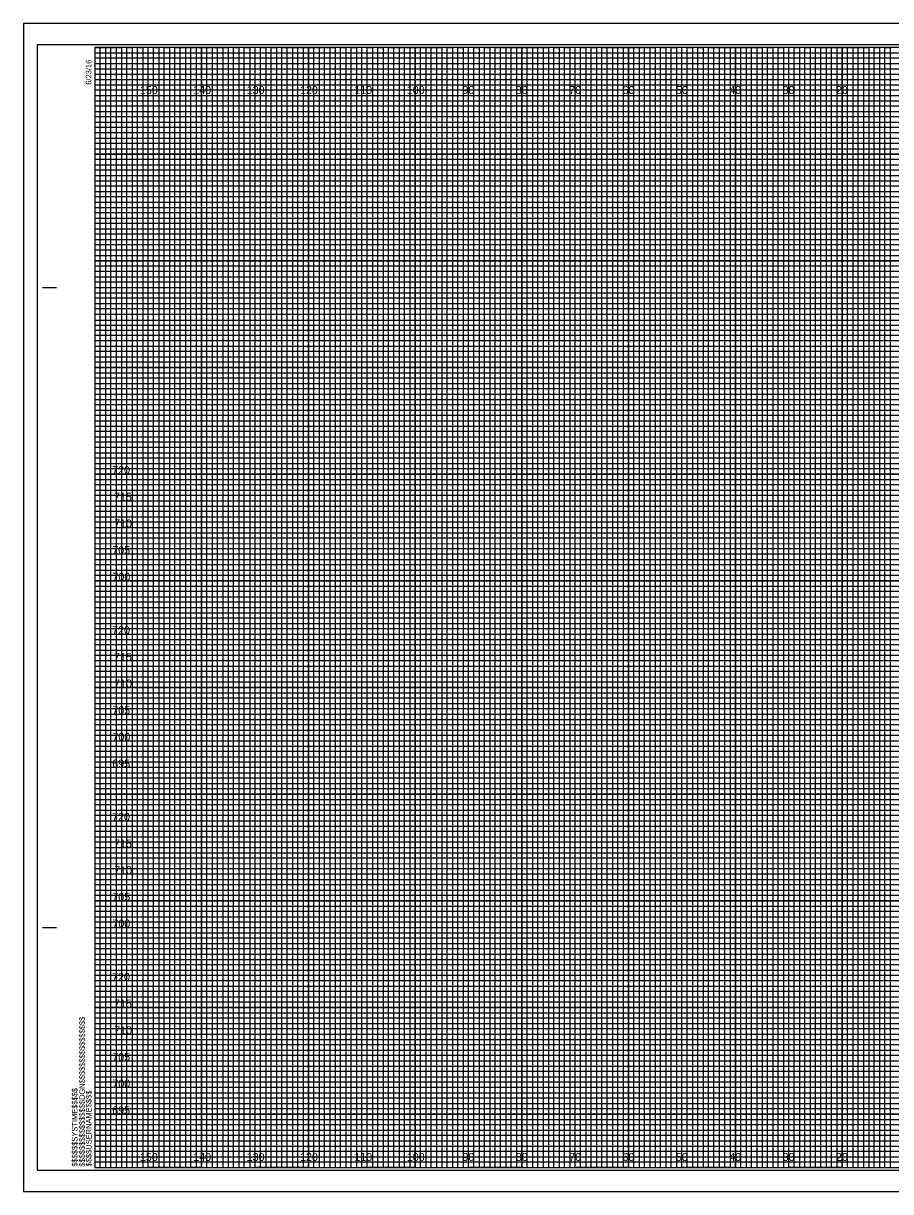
# Model space of a CAD drawing. Extents: x -13 to 323, y -5 to 434.
# Drawn here: x -13.4 to 149.1, y 215.5 to 434.5 of the extents above; entities that cross this region are included whole.
import ezdxf

# ---------------------------------------------------------------- set-up
doc = ezdxf.new("R2010")
doc.units = 0
for name, color, linetype in [('Exist CMT Pavement', 7, 'Continuous'), ('Exist Cross Section Cell', 7, 'Continuous'), ('Exist XS Center Line Elevation Label', 7, 'Continuous'), ('Exist XS Ground Line', 7, 'Continuous'), ('Prop CMT Pvmt Course 1 Wedge', 7, 'Continuous'), ('Prop CMT Pvmt Course 2', 7, 'Continuous'), ('Prop CMT Pvmt Course 3', 7, 'Continuous'), ('Prop CMT Shld Paved Course 1', 7, 'Continuous'), ('Prop CMT Shld Paved Course 2', 7, 'Continuous'), ('Prop CMT Subgrade Earthwork', 7, 'Continuous'), ('Scratch_Level_1', 7, 'Continuous')]:
    doc.layers.add(name, color=color, linetype=linetype)

msp = doc.modelspace()

# ---------------------------------------------------------------- linework, layer by layer
at = {"layer": 'Exist XS Center Line Elevation Label'}
for points in [[(0, 430), (5, 430), (5, 220), (15, 220), (15, 430), (25, 430), (25, 220), (35, 220), (35, 430), (45, 430), (45, 220), (55, 220), (55, 430), (65, 430), (65, 220), (75, 220), (75, 430), (85, 430), (85, 220), (95, 220), (95, 430), (105, 430), (105, 220), (115, 220), (115, 430), (125, 430), (125, 220), (135, 220), (135, 430), (145, 430), (145, 220), (155, 220)], [(0, 425), (275, 425)], [(0, 405), (320, 405), (320, 415), (0, 415)], [(0, 385), (320, 385), (320, 395), (0, 395)], [(0, 365), (320, 365), (320, 375), (0, 375)], [(0, 345), (320, 345), (320, 355), (0, 355)], [(0, 325), (320, 325), (320, 335), (0, 335)], [(0, 305), (320, 305), (320, 315), (0, 315)], [(0, 285), (320, 285), (320, 295), (0, 295)], [(0, 265), (320, 265), (320, 275), (0, 275)], [(0, 245), (320, 245), (320, 255), (0, 255)], [(0, 225), (320, 225), (320, 235), (0, 235)]]:
    msp.add_lwpolyline(points, dxfattribs=at)
at = {"layer": 'Exist XS Ground Line'}
for p, q in [((10, 430), (0, 430)), ((10, 220), (10, 430)), ((30, 430), (20, 430)), ((20, 430), (20, 220)), ((30, 220), (30, 430)), ((50, 430), (40, 430)), ((40, 430), (40, 220)), ((50, 220), (50, 430)), ((70, 430), (60, 430)), ((60, 430), (60, 220)), ((70, 220), (70, 430)), ((90, 430), (80, 430)), ((80, 430), (80, 220)), ((90, 220), (90, 430)), ((110, 430), (100, 430)), ((100, 430), (100, 220)), ((110, 220), (110, 430)), ((130, 430), (120, 430)), ((120, 430), (120, 220)), ((130, 220), (130, 430)), ((150, 430), (140, 430)), ((140, 430), (140, 220)), ((20, 220), (10, 220)), ((40, 220), (30, 220)), ((60, 220), (50, 220)), ((80, 220), (70, 220)), ((100, 220), (90, 220)), ((120, 220), (110, 220)), ((140, 220), (130, 220))]:
    msp.add_line(p, q, dxfattribs=at)
for points in [[(0, 420), (320, 420), (320, 410), (0, 410)], [(0, 400), (320, 400), (320, 390), (0, 390)], [(0, 380), (320, 380), (320, 370), (0, 370)], [(0, 360), (320, 360), (320, 350), (0, 350)], [(0, 340), (320, 340), (320, 330), (0, 330)], [(0, 320), (320, 320), (320, 310), (0, 310)], [(0, 300), (320, 300), (320, 290), (0, 290)], [(0, 280), (320, 280), (320, 270), (0, 270)], [(0, 260), (320, 260), (320, 250), (0, 250)], [(0, 240), (320, 240), (320, 230), (0, 230)]]:
    msp.add_lwpolyline(points, dxfattribs=at)
at = {"layer": 'Prop CMT Pvmt Course 1 Wedge'}
for p, q in [((323.3, 434.5), (-13.4, 434.5)), ((-13.4, 434.5), (-13.4, 215.5)), ((-13.4, 215.5), (323.3, 215.5))]:
    msp.add_line(p, q, dxfattribs=at)
at = {"layer": 'Prop CMT Pvmt Course 2'}
msp.add_lwpolyline([(-13.4, 215.5), (323.3, 215.5), (323.3, 434.5), (-13.4, 434.5)], close=True, dxfattribs=at)
at = {"layer": 'Prop CMT Pvmt Course 3'}
msp.add_lwpolyline([(-10.8, 219.5), (322.4, 219.5), (322.4, 430.5), (-10.8, 430.5)], close=True, dxfattribs=at)
at = {"layer": 'Prop CMT Shld Paved Course 1'}
for p, q in [((-9.8, 385), (-7.3, 385)), ((-9.7, 385), (-7.2, 385)), ((-9.8, 265), (-7.3, 265)), ((-9.7, 265), (-7.2, 265)), ((0, 220), (0, 220)), ((0, 220), (0, 220)), ((0, 220), (0, 220)), ((0, 220), (0, 220)), ((0, 220), (0, 220)), ((0, 220), (0, 220)), ((0, 220), (0, 220))]:
    msp.add_line(p, q, dxfattribs=at)
msp.add_lwpolyline([(320, 430), (0, 430), (0, 220), (320, 220)], close=True, dxfattribs=at)
at = {"layer": 'Prop CMT Shld Paved Course 2'}
for points in [[(0, 220), (1, 220), (1, 430), (2, 430), (2, 220)], [(2, 220), (3, 220), (3, 430), (4, 430), (4, 220)], [(5, 220), (6, 220), (6, 430), (7, 430), (7, 220)], [(7, 220), (8, 220), (8, 430), (9, 430), (9, 220)], [(10, 220), (11, 220), (11, 430), (12, 430), (12, 220)], [(12, 220), (13, 220), (13, 430), (14, 430), (14, 220)], [(15, 220), (16, 220), (16, 430), (17, 430), (17, 220)], [(17, 220), (18, 220), (18, 430), (19, 430), (19, 220)], [(20, 220), (21, 220), (21, 430), (22, 430), (22, 220)], [(22, 220), (23, 220), (23, 430), (24, 430), (24, 220)], [(25, 220), (26, 220), (26, 430), (27, 430), (27, 220)], [(27, 220), (28, 220), (28, 430), (29, 430), (29, 220)], [(30, 220), (31, 220), (31, 430), (32, 430), (32, 220)], [(32, 220), (33, 220), (33, 430), (34, 430), (34, 220)], [(35, 220), (36, 220), (36, 430), (37, 430), (37, 220)], [(37, 220), (38, 220), (38, 430), (39, 430), (39, 220)], [(40, 220), (41, 220), (41, 430), (42, 430), (42, 220)], [(42, 220), (43, 220), (43, 430), (44, 430), (44, 220)], [(45, 220), (46, 220), (46, 430), (47, 430), (47, 220)], [(47, 220), (48, 220), (48, 430), (49, 430), (49, 220)], [(50, 220), (51, 220), (51, 430), (52, 430), (52, 220)], [(52, 220), (53, 220), (53, 430), (54, 430), (54, 220)], [(55, 220), (56, 220), (56, 430), (57, 430), (57, 220)], [(57, 220), (58, 220), (58, 430), (59, 430), (59, 220)], [(60, 220), (61, 220), (61, 430), (62, 430), (62, 220)], [(62, 220), (63, 220), (63, 430), (64, 430), (64, 220)], [(65, 220), (66, 220), (66, 430), (67, 430), (67, 220)], [(67, 220), (68, 220), (68, 430), (69, 430), (69, 220)], [(70, 220), (71, 220), (71, 430), (72, 430), (72, 220)], [(72, 220), (73, 220), (73, 430), (74, 430), (74, 220)], [(75, 220), (76, 220), (76, 430), (77, 430), (77, 220)], [(77, 220), (78, 220), (78, 430), (79, 430), (79, 220)], [(80, 220), (81, 220), (81, 430), (82, 430), (82, 220)], [(82, 220), (83, 220), (83, 430), (84, 430), (84, 220)], [(85, 220), (86, 220), (86, 430), (87, 430), (87, 220)], [(87, 220), (88, 220), (88, 430), (89, 430), (89, 220)], [(90, 220), (91, 220), (91, 430), (92, 430), (92, 220)], [(92, 220), (93, 220), (93, 430), (94, 430), (94, 220)], [(95, 220), (96, 220), (96, 430), (97, 430), (97, 220)], [(97, 220), (98, 220), (98, 430), (99, 430), (99, 220)], [(100, 220), (101, 220), (101, 430), (102, 430), (102, 220)], [(102, 220), (103, 220), (103, 430), (104, 430), (104, 220)], [(105, 220), (106, 220), (106, 430), (107, 430), (107, 220)], [(107, 220), (108, 220), (108, 430), (109, 430), (109, 220)], [(110, 220), (111, 220), (111, 430), (112, 430), (112, 220)], [(112, 220), (113, 220), (113, 430), (114, 430), (114, 220)], [(115, 220), (116, 220), (116, 430), (117, 430), (117, 220)], [(117, 220), (118, 220), (118, 430), (119, 430), (119, 220)], [(120, 220), (121, 220), (121, 430), (122, 430), (122, 220)], [(122, 220), (123, 220), (123, 430), (124, 430), (124, 220)], [(125, 220), (126, 220), (126, 430), (127, 430), (127, 220)], [(127, 220), (128, 220), (128, 430), (129, 430), (129, 220)], [(130, 220), (131, 220), (131, 430), (132, 430), (132, 220)], [(132, 220), (133, 220), (133, 430), (134, 430), (134, 220)], [(135, 220), (136, 220), (136, 430), (137, 430), (137, 220)], [(137, 220), (138, 220), (138, 430), (139, 430), (139, 220)], [(140, 220), (141, 220), (141, 430), (142, 430), (142, 220)], [(142, 220), (143, 220), (143, 430), (144, 430), (144, 220)], [(145, 220), (146, 220), (146, 430), (147, 430), (147, 220)], [(147, 220), (148, 220), (148, 430), (149, 430), (149, 220)]]:
    msp.add_lwpolyline(points, dxfattribs=at)
at = {"layer": 'Prop CMT Subgrade Earthwork'}
for p, q in [((10, 220), (10, 430)), ((20, 220), (20, 430)), ((30, 220), (30, 430)), ((40, 220), (40, 430)), ((50, 220), (50, 430)), ((60, 220), (60, 430)), ((70, 220), (70, 430)), ((80, 220), (80, 430)), ((90, 220), (90, 430)), ((100, 220), (100, 430)), ((110, 220), (110, 430)), ((120, 220), (120, 430)), ((130, 220), (130, 430)), ((140, 220), (140, 430)), ((0, 420), (320, 420)), ((0, 410), (320, 410)), ((0, 400), (320, 400)), ((0, 390), (320, 390)), ((0, 380), (320, 380)), ((0, 370), (320, 370)), ((0, 360), (320, 360)), ((0, 350), (320, 350)), ((0, 340), (320, 340)), ((0, 330), (320, 330)), ((0, 320), (320, 320)), ((0, 310), (320, 310)), ((0, 300), (320, 300)), ((0, 290), (320, 290)), ((0, 280), (320, 280)), ((0, 270), (320, 270)), ((0, 260), (320, 260)), ((0, 250), (320, 250)), ((0, 240), (320, 240)), ((0, 230), (320, 230))]:
    msp.add_line(p, q, dxfattribs=at)
at = {"layer": 'Scratch_Level_1'}
for p, q in [((0, 429), (260, 429)), ((260, 427.98), (0, 427.98)), ((0, 427.98), (0, 427)), ((0, 427), (260, 427)), ((260, 425.89), (0, 425.89)), ((0, 425.89), (0, 424)), ((0, 424), (320, 424))]:
    msp.add_line(p, q, dxfattribs=at)
for points in [[(0, 423), (270, 423), (320, 423), (320, 422), (0, 422)], [(0, 421), (320, 421), (320, 419), (0, 419)], [(0, 418), (320, 418), (320, 417), (0, 416.98)], [(0, 416), (320, 416), (320, 414), (0, 414)], [(0, 413), (320, 413), (320, 412), (0, 412)], [(0, 411), (320, 411), (320, 409), (0, 409)], [(0, 408), (320, 408), (320, 407), (0, 407)], [(0, 406), (320, 406), (320, 404), (0, 404)], [(0, 403), (320, 403), (320, 402), (0, 402)], [(0, 401), (320, 401), (320, 399), (0, 399)], [(0, 398), (320, 398), (320, 397), (0, 397)], [(0, 396), (320, 396), (320, 393.95), (320, 393), (320, 392), (0, 392)], [(0, 394), (320, 394), (320, 393), (0, 393)], [(0, 391), (320, 391), (320, 389), (0, 389.03)], [(0, 389.03), (320, 389), (320, 388), (0, 388)], [(0, 387), (320, 387), (320, 386), (0, 386)], [(0, 384), (320, 384), (320, 383), (0, 383)], [(0, 382), (320, 382), (320, 381), (0, 381)], [(-0.07, 378.89), (320, 378.89), (320, 377.88), (-0.07, 377.88)], [(0, 377), (320, 377), (320, 376), (0, 376)], [(0, 374), (320, 374), (320, 373), (0, 373)], [(0, 372), (320, 372), (320, 371), (0, 371)], [(0, 369), (320, 369), (320, 368), (0, 368)], [(0, 367), (320, 367), (320, 366), (0, 366)], [(0, 364), (320, 364), (320, 363), (0, 363)], [(0, 362), (320, 362), (320, 361), (0, 361)], [(0, 359), (320, 359), (319.99, 357.98), (0, 358)], [(0, 357), (320, 357), (320, 356), (0, 356)], [(0, 354), (320, 354), (320, 353), (0, 353)], [(0, 352), (320, 352), (320, 351), (0, 351)], [(0, 349), (320, 349), (320, 348), (0, 348)], [(0, 347), (320, 347), (320, 346), (0, 346)], [(0, 344), (320, 344), (320, 343), (0, 343)], [(0, 342), (320, 342), (320, 341), (0, 341)], [(0, 339), (320, 339), (320, 338), (0, 338)], [(0, 336.99), (320.07, 336.91), (320, 336), (0, 336)], [(0, 334), (320, 334), (320, 333), (0, 333)], [(0, 332), (320, 332), (320, 331), (0, 331)], [(0, 329), (320, 329), (320, 328), (0, 328)], [(0, 327), (320, 327), (320, 326), (0, 326)], [(0, 324), (320, 324), (320, 323), (0, 323)], [(0, 322), (320, 322), (320, 321), (0, 321)], [(0, 319), (320, 319), (320, 318), (0, 318)], [(0, 317), (320, 317), (320, 316), (0, 316)], [(0, 314), (320, 314), (320, 313), (0, 313)], [(0, 312), (320, 312), (320, 311), (0, 311)], [(0, 309), (320, 309), (320, 308), (0, 308)], [(0, 307), (320, 307), (320, 306), (0, 306)], [(0, 304), (320, 304), (320, 303), (0, 303)], [(0, 302), (320, 302), (320, 301), (0, 301)], [(0, 299), (320, 299), (319.99, 297.98), (0, 298)], [(0, 297), (320, 297), (320, 296), (0, 296)], [(0, 294), (320, 294), (320, 293), (0, 293)], [(0, 292), (320, 292), (320, 291), (0, 291)], [(0, 289), (320, 289), (320, 288), (0, 288)], [(0, 287), (320, 287), (320, 286), (0, 286)], [(0, 284), (320, 284), (320, 283), (0, 283)], [(0, 282), (320, 282), (320, 281), (0, 281)], [(0, 279), (320, 279), (320, 278), (0, 278)], [(0, 276.99), (320.07, 276.91), (320, 276), (0, 276)], [(0, 274), (320, 274), (320, 273), (0, 273)], [(0, 272), (320, 272), (320, 271), (0, 271)], [(0, 269), (320, 269), (320, 268), (0, 268)], [(0, 267), (320, 267), (320, 266), (0, 266)], [(0, 264), (320, 264), (320, 263), (0, 263)], [(0, 262), (320, 262), (320, 261), (0, 261)], [(0, 259), (320, 259), (320, 258), (0, 258)], [(0, 257), (320, 257), (320, 256), (0, 256)], [(0, 254), (320, 254), (320, 253), (0, 253)], [(0, 252), (320, 252), (320, 251), (0, 251)], [(0, 249), (320, 249), (320, 248), (0, 248)], [(0, 247), (320, 247), (320, 246), (0, 246)], [(0, 244), (320, 244), (320, 243), (0, 243)], [(0, 242), (320, 242), (320, 241), (0, 241)], [(0, 239), (320, 239), (320, 238), (0, 238)], [(0, 237), (320, 237), (320, 236), (0, 236)], [(0, 234), (320, 234), (320, 233), (0, 233)], [(0, 232), (320, 232), (320, 231), (0, 231)], [(0, 229), (320, 229), (320, 228), (0, 228)], [(0, 227), (320, 227), (320, 226), (0, 226)], [(0, 224), (320, 224), (320, 223), (0, 223)], [(0, 222), (320, 222), (320, 221), (0, 221)]]:
    msp.add_lwpolyline(points, dxfattribs=at)

# ---------------------------------------------------------------- texts
at = {"layer": 'Exist CMT Pavement'}
for s, p in [('720', (3.23, 350)), ('715', (3.59, 345)), ('710', (3.61, 340)), ('705', (3.26, 335)), ('700', (3.28, 330)), ('720', (3.23, 320)), ('715', (3.59, 315)), ('710', (3.61, 310)), ('705', (3.26, 305)), ('700', (3.28, 300)), ('695', (3.25, 295)), ('720', (3.23, 285)), ('715', (3.59, 280)), ('710', (3.61, 275)), ('705', (3.26, 270)), ('700', (3.28, 265)), ('720', (3.23, 255)), ('715', (3.59, 250)), ('710', (3.61, 245)), ('705', (3.26, 240)), ('700', (3.28, 235)), ('695', (3.25, 230))]:
    msp.add_text(s, height=1.5, dxfattribs=at).set_placement(p)
at = {"layer": 'Exist Cross Section Cell'}
for s, p in [('150', (8.44, 421.25)), ('140', (18.44, 421.25)), ('130', (28.44, 421.25)), ('120', (38.44, 421.25)), ('110', (48.62, 421.25)), ('100', (58.44, 421.25)), ('90', (68.86, 421.25)), ('80', (78.86, 421.25)), ('70', (88.86, 421.25)), ('60', (98.86, 421.25)), ('50', (108.86, 421.25)), ('40', (118.86, 421.25)), ('30', (128.86, 421.25)), ('20', (138.86, 421.25)), ('150', (8.44, 221.25)), ('140', (18.44, 221.25)), ('130', (28.44, 221.25)), ('120', (38.44, 221.25)), ('110', (48.62, 221.25)), ('100', (58.44, 221.25)), ('90', (68.86, 221.25)), ('80', (78.86, 221.25)), ('70', (88.86, 221.25)), ('60', (98.86, 221.25)), ('50', (108.86, 221.25)), ('40', (118.86, 221.25)), ('30', (128.86, 221.25)), ('20', (138.86, 221.25))]:
    msp.add_text(s, height=1.5, dxfattribs=at).set_placement(p)
at = {"layer": 'Prop CMT Shld Paved Course 1'}
for s, p in [('6/23/16', (-0.65, 423)), ('$$$$$$$$$$$$$$$$DGN$$$$$$$$$$$$$$$$', (-1.88, 220.18)), ('$$$$$$SYSTIME$$$$$', (-3.26, 220.18)), ('$$$$USERNAME$$$$', (-0.62, 220.23))]:
    msp.add_text(s, height=1.05, rotation=90, dxfattribs=at).set_placement(p)

doc.saveas('drawing.dxf')
